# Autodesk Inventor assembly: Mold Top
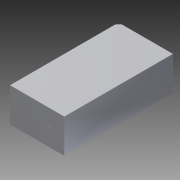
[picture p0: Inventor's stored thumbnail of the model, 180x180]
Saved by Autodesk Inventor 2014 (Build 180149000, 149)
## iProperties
Created: 2009-12
Part Number: Mold Top
Document SubType Name: Assembly
Designer: gaom
Author: gaom
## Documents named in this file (2)
- C:\Users\iTools\Desktop\tutorial files\Mold\Mold Structural Assembly\Mold Top\Mold Top.iam
- C:\Users\iTools\Desktop\tutorial files\Mold\Mold Structural Assembly\Mold Top\Mold Top_Top_LY.iam
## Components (1 placed, 1 different names)
1. Mold Top_Top_LY:1 [sub-assembly] — Flush:1, Flush:2, Flush:3
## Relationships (3: Flush 3)
- Flush:1: Mold Top_Top_LY:1
- Flush:2: Mold Top_Top_LY:1
- Flush:3: Mold Top_Top_LY:1
